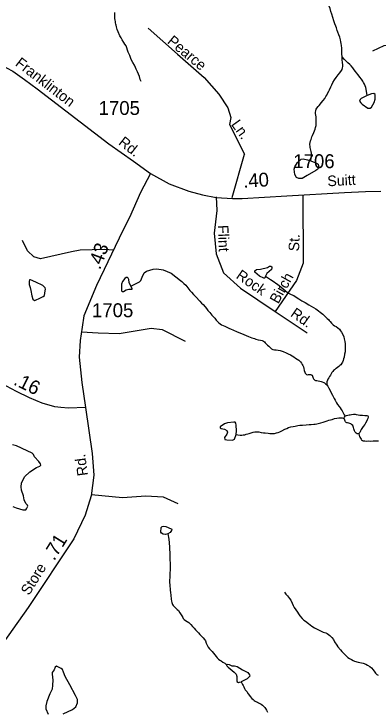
# Model space of a CAD drawing. Extents: x 2056842 to 2160602, y 826753 to 1016856.
# Drawn here: x 2133459 to 2136734, y 858350 to 864623 of the extents above; entities that cross this region are included whole.
import ezdxf

# ---------------------------------------------------------------- set-up
doc = ezdxf.new("R2010")
doc.units = 0
for name, color, linetype in [('Exist Hydrographic Creek Single Shore', 7, 'Continuous'), ('Exist Hydrographic Misc Water Feature', 7, 'Continuous'), ('Exist Road Non-System Type 51', 7, 'Continuous'), ('Exist Road Non-System Type 51 Label', 7, 'Continuous'), ('Exist Road Secondary Mileage Hundredths English Label', 7, 'Continuous'), ('Exist Road Secondary Type 51 Attributed', 7, 'Continuous'), ('Exist Road Secondary Type 51 Label', 7, 'Continuous'), ('Exist Road Secondary Type 51 Number Label', 7, 'Continuous')]:
    doc.layers.add(name, color=color, linetype=linetype)

msp = doc.modelspace()

# ---------------------------------------------------------------- linework, layer by layer
at = {"layer": 'Exist Hydrographic Creek Single Shore'}
for points in [[(2134842.5, 859943.7), (2134851, 859895.1), (2134858.3, 859827), (2134862, 859754), (2134865.6, 859637.3), (2134859.6, 859505.7), (2134860, 859486), (2134864.5, 859438.3), (2134866.5, 859416.1), (2134868.8, 859393.9), (2134873.1, 859357.7), (2134875.4, 859339.7), (2134879.5, 859326.5), (2134885.6, 859310), (2134891.6, 859300), (2134897.9, 859292.4), (2134909.8, 859280.8), (2134927.9, 859264.8), (2134937.9, 859254.8), (2134950.4, 859234.8), (2134958.2, 859223.1), (2134968.5, 859206.5), (2134976.7, 859190.8), (2134982.6, 859183.2), (2134990.6, 859174.9), (2135002.9, 859164.8), (2135016.9, 859155.5), (2135032.8, 859145.3), (2135049.2, 859129.4), (2135065.2, 859111.8), (2135079.4, 859095.9), (2135093.3, 859080.1), (2135105.6, 859065.9), (2135117.7, 859053.3), (2135129.8, 859040), (2135146.2, 859024.1), (2135161.6, 859008.1), (2135172.5, 858994.9), (2135180.5, 858980.7), (2135188.7, 858960.8), (2135196.7, 858942.6), (2135206.9, 858925.2), (2135217.2, 858911), (2135229.5, 858897.7), (2135241.2, 858885.2), (2135255.1, 858869.3), (2135265.6, 858855.1), (2135277.1, 858840.1), (2135287.9, 858830), (2135299.8, 858817.4), (2135311.9, 858808.2), (2135323, 858800.6), (2135338.2, 858790.5), (2135354.4, 858780.3), (2135369.1, 858770.1)], [(2135369.1, 858770.1), (2135377.3, 858771.4), (2135395.5, 858768.9), (2135419.8, 858758), (2135442.9, 858758), (2135467.2, 858750.7), (2135514.6, 858720.3), (2135563.3, 858697.2), (2135577.8, 858675.3), (2135580.3, 858664.4), (2135573, 858653.4), (2135557.2, 858640), (2135520.7, 858620.6), (2135503.8, 858613.2)], [(2135369.1, 858770.1), (2135374.9, 858758), (2135387, 858743.4), (2135439.3, 858698.4), (2135458.7, 858681.4), (2135463.6, 858659.5), (2135464.8, 858616.9), (2135478.2, 858607.2), (2135489.1, 858608.4), (2135503.8, 858613.2)], [(2135503.8, 858613.2), (2135515.9, 858589.9), (2135519.8, 858580), (2135526.4, 858566.7), (2135534.2, 858551.8), (2135540.1, 858541.8), (2135552.4, 858524.3), (2135566.6, 858504.4), (2135578.7, 858488.5), (2135584.8, 858480.2), (2135598.6, 858463.5), (2135609.9, 858453.5), (2135618.7, 858445.1), (2135630, 858439.1), (2135641.2, 858433.2), (2135649.2, 858428.9), (2135658.9, 858423.7), (2135669.3, 858418.6), (2135682.2, 858411.8), (2135693.3, 858403.3), (2135703.6, 858394.9), (2135715.7, 858381.5), (2135721.6, 858373.2), (2135731.9, 858357.4), (2135740.1, 858339.2)]]:
    msp.add_lwpolyline(points, dxfattribs=at)
at = {"layer": 'Exist Hydrographic Misc Water Feature'}
for points in [[(2136411.2, 864238.2), (2136409.2, 864264.5), (2136408.9, 864292.5), (2136406.7, 864314.6), (2136404.4, 864340.1), (2136402.4, 864356.6), (2136399.3, 864373.1), (2136395.4, 864390.3), (2136388.9, 864415.1), (2136381.7, 864435.7), (2136373.5, 864458.1), (2136367.3, 864473.7), (2136358.9, 864497.6), (2136353.2, 864511.7), (2136344.2, 864532.8), (2136334.7, 864560.5), (2136325.9, 864589.6), (2136317.1, 864619.4), (2136308.7, 864645.9), (2136301.7, 864670.9), (2136294.7, 864692.7), (2136277.7, 864722.1), (2136255.4, 864746), (2136226.7, 864772.8)], [(2134602.2, 864014.8), (2134595.9, 864033), (2134587.7, 864060.3), (2134579.7, 864080.1), (2134570.5, 864102.4), (2134559.2, 864126.4), (2134551.2, 864142.2), (2134543, 864160.4), (2134528.6, 864186.2), (2134514.5, 864214.3), (2134506.1, 864231.7), (2134500.1, 864249.8), (2134494, 864265.5), (2134487.8, 864279.7), (2134481.7, 864297.8), (2134475.7, 864317.6), (2134467.3, 864335.8), (2134457.1, 864351.6), (2134447.2, 864365.8), (2134432.9, 864389.1), (2134422.8, 864407.3), (2134412.6, 864427.2), (2134396.4, 864461.1), (2134388.2, 864482.7), (2134381.2, 864507.1), (2134377.9, 864522.3), (2134375.7, 864532.1), (2134373.6, 864543.5), (2134371.3, 864553.8), (2134369.1, 864566.7), (2134367.5, 864582), (2134366.8, 864600.4), (2134366.6, 864618), (2134366.6, 864637.3)], [(2136129, 863301.5), (2136135.2, 863351.6), (2136135.2, 863369.6), (2136132.9, 863383.6), (2136129.9, 863396.8), (2136126.6, 863409.9), (2136124.5, 863419.9), (2136122.5, 863432.2), (2136120.4, 863443.8), (2136120.4, 863452), (2136122.1, 863465.8), (2136126.2, 863479.7), (2136131.9, 863493.5), (2136139.7, 863515.5), (2136145.7, 863530.1), (2136155.3, 863556.2), (2136161, 863571.6), (2136167.2, 863586.3), (2136171.1, 863600.1), (2136176.8, 863619.8), (2136178.7, 863638.6), (2136178.5, 863654.2), (2136178.5, 863666.5), (2136178.5, 863682), (2136176.2, 863696), (2136174, 863712.5), (2136171.9, 863726.4), (2136172.1, 863739.6), (2136173.5, 863750.2), (2136178.1, 863765.7), (2136183.4, 863776.3), (2136195.1, 863790), (2136203.1, 863798), (2136215.2, 863812.6), (2136223, 863822.2), (2136240.2, 863843.1), (2136254.5, 863862.5), (2136264.6, 863878.8), (2136272.4, 863893.3), (2136280.4, 863907.2), (2136290.2, 863927.5), (2136296, 863939.7), (2136309.7, 863967.2), (2136319.5, 863985.9), (2136328.4, 864004.6), (2136342.7, 864028.9), (2136357.5, 864051.5), (2136374.9, 864074.1), (2136388.6, 864091.9), (2136404.4, 864114.5), (2136410.4, 864124.2), (2136414.5, 864137.3), (2136416.1, 864150.4), (2136415.9, 864161.9), (2136413.7, 864188.1), (2136411.6, 864207.9), (2136411.4, 864221.8), (2136411.2, 864238.2)], [(2136635.9, 863890.1), (2136627.9, 863945.9), (2136623.4, 863960.7), (2136617.5, 863975.7), (2136611.3, 863989.7), (2136603.3, 864006.3), (2136597.2, 864017.8), (2136586.1, 864035.3), (2136570.9, 864055.3), (2136556, 864074.5), (2136540.4, 864093.7), (2136532.4, 864105.4), (2136520.3, 864121.2), (2136506.1, 864138.7), (2136491.8, 864157), (2136479.9, 864168.7), (2136461.6, 864183.1), (2136453.7, 864190.7), (2136443.6, 864200.6), (2136431.3, 864214), (2136411.2, 864238.2)], [(2136635.9, 863890.1), (2136582.4, 863863.4), (2136573.9, 863852.4), (2136567.8, 863839.1), (2136577.5, 863822), (2136589.7, 863809.9), (2136643.2, 863774.6), (2136661.4, 863774.6), (2136673.5, 863783.1), (2136700.3, 863826.9), (2136707.6, 863857.3), (2136706.4, 863898.6), (2136695.4, 863908.4), (2136673.5, 863904.7), (2136635.9, 863890.1)], [(2136129, 863301.5), (2136186.2, 863278.4), (2136194.7, 863269.9), (2136198.3, 863257.7), (2136198.3, 863245.6), (2136191, 863227.3), (2136172.8, 863212.7), (2136096.2, 863167.7), (2136050, 863143.4), (2136020.9, 863141), (2136001.4, 863150.7), (2135986.8, 863178.7), (2135978.3, 863226.1), (2135984.4, 863246.8), (2136009.9, 863286.9), (2136041.5, 863317.3), (2136059.7, 863319.8), (2136098.6, 863311.2), (2136129, 863301.5)], [(2134510.9, 862172.9), (2134587.5, 862211.9), (2134599.7, 862224), (2134611.8, 862253.2), (2134631.9, 862293.3), (2134650.1, 862307.9), (2134712.1, 862327.4), (2134744.9, 862329.8), (2134800.8, 862318.9), (2134872.5, 862290.9), (2134955.9, 862225.1), (2134967.8, 862215.1), (2134987.9, 862197.5), (2135004.1, 862181.6), (2135024.4, 862158.2), (2135042.5, 862134), (2135056.6, 862118.1), (2135074.9, 862098), (2135095, 862076.3), (2135131.5, 862038.7), (2135145.6, 862021.1), (2135159.6, 862007), (2135177.8, 861986.9), (2135190.1, 861971), (2135204.1, 861953.5), (2135220.1, 861935.9), (2135238.3, 861913.5), (2135264.6, 861884.1), (2135278.9, 861868.3), (2135290.8, 861854.1), (2135302.9, 861842.3), (2135313.2, 861834.7), (2135325.9, 861826.3), (2135354.4, 861812.6), (2135393.3, 861795.4), (2135411.6, 861787.6), (2135427.6, 861781.5), (2135467.6, 861763.5), (2135489.9, 861754), (2135526, 861738.5), (2135546.3, 861729.8), (2135568.2, 861720.4), (2135582.2, 861714.4), (2135598.2, 861709.1), (2135622.2, 861701.2), (2135634.1, 861696.8), (2135656.4, 861691.5), (2135676.3, 861687.8), (2135692.3, 861683.4), (2135704.6, 861678.3), (2135711.2, 861672.3), (2135718.7, 861664), (2135726.7, 861654), (2135738.8, 861642.3), (2135750.9, 861632.1), (2135759.1, 861624.7), (2135769.2, 861616.1), (2135777, 861610.3), (2135787.2, 861604.4), (2135801.2, 861600.8), (2135817.2, 861598.8), (2135835.6, 861596.8), (2135853.1, 861593.1), (2135879.1, 861585.2), (2135907.4, 861573.9), (2135925.4, 861565.4), (2135945.7, 861554.3), (2135961.7, 861545.7), (2135977.7, 861536.5), (2135991.9, 861526.2), (2136020, 861506.8), (2136036, 861492.6), (2136046.2, 861479.3), (2136052.4, 861469.2), (2136058.3, 861459.3), (2136063.4, 861446.1), (2136066.7, 861431.3), (2136070.4, 861415.6), (2136074.9, 861400.7), (2136078.4, 861391.6), (2136083.7, 861384.1), (2136091.7, 861378.2), (2136101.6, 861376.3), (2136108.1, 861377.1), (2136114.7, 861378.6), (2136121.7, 861379.2), (2136127.8, 861379.1), (2136133.6, 861376.5), (2136141.6, 861371.4)], [(2135722.5, 862262.9), (2135715.2, 862245.9), (2135706.7, 862244.7), (2135667.8, 862261.7), (2135626.5, 862299.4), (2135626.5, 862311.6), (2135639.8, 862322.5), (2135677.5, 862327.4), (2135739.5, 862342), (2135758.9, 862352.9), (2135768.7, 862352.9), (2135777.2, 862346.8), (2135779.6, 862335.9), (2135774.7, 862322.5), (2135734.6, 862287.3), (2135727.3, 862276.3), (2135722.5, 862262.9)], [(2134510.9, 862172.9), (2134496, 862205.2), (2134492.4, 862233.7), (2134487.5, 862245.9), (2134479.6, 862251.4), (2134467.5, 862251.4), (2134455.3, 862242.9), (2134434.7, 862216.1), (2134426.2, 862192.4), (2134426.2, 862172.9), (2134428, 862131), (2134435.3, 862125.5), (2134443.8, 862126.1), (2134468.1, 862140.1), (2134493, 862147.4), (2134518.5, 862145), (2134522.2, 862147.4), (2134521.6, 862152.9), (2134510.9, 862172.9)], [(2135722.5, 862262.9), (2135767.3, 862232.2), (2135799.7, 862211), (2135815.9, 862200.8), (2135829.9, 862190.7), (2135862.1, 862163), (2135898.4, 862133.5), (2135922.6, 862114.2), (2135934.7, 862105.7), (2135952.7, 862097.9), (2135975.1, 862087.7), (2135996.8, 862074.8), (2136022.4, 862059.7), (2136049.1, 862042.6), (2136077.4, 862027.3), (2136111.6, 862005.2), (2136131.7, 861993.3), (2136174, 861967.9), (2136198, 861950.2), (2136214.1, 861938.4), (2136236.1, 861920.6), (2136248.4, 861909), (2136260.5, 861897.2), (2136276.7, 861882.9), (2136286.7, 861872.9), (2136294.7, 861865.3), (2136302.9, 861855.3), (2136315.2, 861841.1), (2136331.2, 861825.2), (2136343.1, 861817.6), (2136357.5, 861809.1), (2136371.4, 861798.1), (2136385.6, 861785.5), (2136395.4, 861772.2), (2136403.6, 861759.8), (2136416.7, 861738.1), (2136426.2, 861716.6), (2136430.1, 861700.1), (2136434.4, 861674.7), (2136437.5, 861653.2), (2136439.3, 861629.4), (2136438.9, 861604), (2136437.5, 861582.7), (2136433.4, 861562.2), (2136427.6, 861534.5), (2136423.7, 861520.6), (2136419.2, 861503.5), (2136414.1, 861490.5), (2136408.1, 861480), (2136398.1, 861466.1), (2136389.9, 861458.1), (2136380, 861450.2), (2136369.2, 861442.2), (2136356.5, 861433.4), (2136350.7, 861429.4), (2136340.7, 861421.4), (2136332.9, 861413.4), (2136326.3, 861406.2), (2136318.9, 861395.7), (2136311.3, 861384.3), (2136305, 861373.1), (2136297.8, 861360.9), (2136290.8, 861349.5), (2136283.5, 861334.9), (2136279.4, 861326.7), (2136273.8, 861311.3), (2136272, 861296.6), (2136272, 861285.1)], [(2133612.1, 862133.6), (2133620.5, 862086.4), (2133630.7, 862055.2), (2133644.1, 862045.1), (2133654.3, 862046.8), (2133691.3, 862066.2), (2133723.4, 862078.8), (2133733.5, 862090.6), (2133736, 862110.9), (2133739.4, 862131.9), (2133743.6, 862147.1), (2133741.1, 862158.1), (2133720, 862180), (2133657.6, 862208.7), (2133607.9, 862231.4), (2133599.5, 862229.8), (2133595.3, 862219.6), (2133595.3, 862186.8), (2133604.5, 862160.6), (2133612.1, 862133.6)], [(2136141.6, 861371.4), (2136145.7, 861362.3), (2136147.9, 861354.9), (2136150.4, 861346.6), (2136153.9, 861339.2), (2136158, 861332.6), (2136165.1, 861327.5), (2136172.1, 861324.9), (2136184.2, 861323), (2136194.1, 861321.2), (2136208.8, 861317.6), (2136221.3, 861314.8), (2136232.2, 861311.3), (2136244.7, 861307), (2136251.7, 861302.7), (2136257.8, 861297.7), (2136265.2, 861291.9), (2136272, 861285.1)], [(2136272, 861285.1), (2136281.8, 861272.6), (2136292.1, 861256.8), (2136302.3, 861235.3), (2136310.3, 861219.5), (2136322.6, 861193), (2136338.8, 861161.5), (2136347.2, 861147.4), (2136359.3, 861123.3), (2136369.4, 861107.6), (2136383.7, 861090), (2136391.9, 861077.6), (2136402, 861064.2), (2136410, 861050.1), (2136424.1, 861026.1), (2136430.1, 861014.4), (2136436.6, 861002.8)], [(2136429.9, 860983.2), (2136429.7, 860989.8), (2136431.3, 860995.6), (2136436.6, 861002.8)], [(2136436.6, 861002.8), (2136441.6, 861006), (2136451.4, 861009.9), (2136461.4, 861012.2), (2136472.7, 861014.4), (2136483.4, 861016.7), (2136494.9, 861018.8), (2136511.5, 861021), (2136527.5, 861020.7), (2136537.3, 861018.7), (2136554.5, 861015.1), (2136571.4, 861013.1), (2136581.4, 861011.3), (2136595.3, 861011), (2136615.4, 861009.8), (2136631.4, 861007.9), (2136641.5, 861005.9), (2136645.4, 861001.8), (2136645.6, 860993.6), (2136641.7, 860981.4), (2136635.9, 860970), (2136631.8, 860961.9), (2136621.8, 860941.5), (2136614.2, 860929.4), (2136600.5, 860909.2), (2136593.9, 860901.1), (2136588.4, 860891.4), (2136582.6, 860882.5), (2136576.7, 860871.1), (2136572.6, 860863), (2136568.9, 860854.9), (2136564.8, 860849.2), (2136559.5, 860846.1)], [(2135458.7, 860837.1), (2135461.2, 860870.4), (2135458.7, 860922.7), (2135455.1, 860939.8), (2135447.8, 860948.3), (2135438.1, 860950.7), (2135379.7, 860942.2), (2135351.8, 860934.9), (2135315.3, 860908.1), (2135315.3, 860899.6), (2135322.6, 860893.5), (2135354.2, 860886.3), (2135374.9, 860874.1), (2135379.7, 860858.3), (2135372.4, 860842.5), (2135354.2, 860812.1), (2135356.6, 860792.6), (2135372.4, 860789), (2135425.9, 860786.5), (2135441.7, 860796.3), (2135458.7, 860837.1)], [(2135458.7, 860837.1), (2135474.1, 860834.9), (2135493.8, 860833.7), (2135508.2, 860833.4), (2135522.1, 860833.9), (2135536, 860836), (2135547.9, 860839.9), (2135561.9, 860844.5), (2135574, 860848.4), (2135591.8, 860854.6), (2135609.5, 860859.2), (2135625.9, 860862.9), (2135643.9, 860863.4), (2135661.7, 860861.3), (2135683.7, 860857.7), (2135703.6, 860854), (2135720, 860851.9), (2135745.8, 860849.8), (2135761.8, 860848.6), (2135783.3, 860847.4), (2135802.2, 860847.8), (2135821.9, 860853.1), (2135834, 860857), (2135849.6, 860863.2), (2135867.4, 860871.1), (2135895.3, 860885.2), (2135913.3, 860893.8), (2135929.3, 860900.1), (2135949.2, 860906.3), (2135970.3, 860911.6), (2135987.2, 860914.5), (2136013.2, 860918.9), (2136029.2, 860921), (2136053.2, 860923), (2136086.8, 860924.7), (2136113.1, 860927.5), (2136133.2, 860929.5), (2136157.1, 860931.5), (2136168.8, 860932.1), (2136182.6, 860934.2), (2136194.9, 860936.4), (2136218.9, 860942.5), (2136239, 860948.7), (2136258.6, 860956.4), (2136274.8, 860962.6), (2136290.6, 860967.3), (2136307, 860971), (2136320.6, 860974.8), (2136342.7, 860981.8), (2136362.6, 860985.5), (2136380.4, 860987.6), (2136392.5, 860988.2), (2136410.4, 860987.8), (2136429.9, 860983.2)], [(2136559.5, 860846.1), (2136552.9, 860844.5), (2136546.3, 860844.7), (2136536.7, 860850.6), (2136526.6, 860860.7), (2136520.7, 860872.3), (2136516.4, 860888.8), (2136514.1, 860901.1), (2136511.1, 860910.2), (2136506.1, 860918.6), (2136496.1, 860928.6), (2136488.1, 860934.5), (2136480.1, 860937.9), (2136470.1, 860940.6), (2136460.2, 860942.4), (2136453.9, 860944.2), (2136447.7, 860947.7), (2136442, 860951.9), (2136437.9, 860957.7), (2136433.6, 860965.9), (2136431.7, 860975.9), (2136429.9, 860983.2)], [(2136559.5, 860846.1), (2136564, 860829.6), (2136565.8, 860823), (2136570.1, 860815.5), (2136576.1, 860805.6), (2136582.2, 860795.5), (2136586.1, 860789.8), (2136594.1, 860783.8), (2136600.5, 860782.1), (2136614.2, 860780.1), (2136632.5, 860779.7), (2136648.4, 860780.2), (2136666.3, 860779.8), (2136690.5, 860780.1), (2136712.4, 860780.6), (2136736.4, 860780.9)], [(2133450.7, 860191.8), (2133478.7, 860179.7), (2133538.2, 860161.4), (2133566.2, 860160.2), (2133573.5, 860169.9), (2133584.4, 860193.1), (2133582, 860201.6), (2133566.2, 860217.4), (2133551.6, 860250.2), (2133544.3, 860287.9), (2133526.1, 860336.6), (2133523.6, 860367), (2133527.3, 860401), (2133555.2, 860458.2), (2133602.6, 860502), (2133661, 860540.9), (2133692.6, 860554.3), (2133699.9, 860562.8), (2133698.7, 860573.7), (2133682.9, 860595.6), (2133642.8, 860638.2), (2133635.5, 860658.8), (2133623.3, 860669.8), (2133579.6, 860690.5), (2133481.1, 860735.5), (2133447.1, 860744)], [(2134842.5, 859943.7), (2134823.1, 859937.7), (2134802.4, 859941.3), (2134785.4, 859951), (2134780.5, 859960.8), (2134782.9, 860000.9), (2134792.7, 860010.6), (2134804.8, 860014.3), (2134824.3, 860011.8), (2134872.9, 859990), (2134877.8, 859985.1), (2134876.5, 859975.4), (2134863.2, 859955.9), (2134842.5, 859943.7)], [(2135892.4, 859418.8), (2135904.7, 859402.9), (2135920.9, 859385.3), (2135936.9, 859363.6), (2135949.2, 859347.9), (2135961.3, 859321.4), (2135971.6, 859299.9), (2135979.6, 859281.6), (2135993.9, 859260), (2136008.1, 859240), (2136018.1, 859224.2), (2136030.4, 859206.7), (2136050.7, 859182.5), (2136066.7, 859168.3), (2136082.7, 859158.9), (2136109, 859138.7), (2136139.1, 859115.1), (2136163.1, 859099.8), (2136191.4, 859083.6), (2136241.6, 859060.5), (2136263.6, 859052.7), (2136275.7, 859046.7), (2136287.6, 859038.2), (2136299.9, 859028.9), (2136318.1, 859010.5), (2136332.1, 858993), (2136342.3, 858971.5), (2136362.6, 858941.5), (2136372.7, 858927.3), (2136394.8, 858899.9), (2136407.1, 858885.6), (2136419.2, 858873.9), (2136429, 858863.9), (2136447.7, 858846.2), (2136461.6, 858832), (2136477.6, 858822.7), (2136493.8, 858812.5), (2136509.8, 858804.8), (2136521.9, 858798.8), (2136554.1, 858789.1), (2136569.9, 858785.5), (2136600.7, 858779.9), (2136624, 858771.2), (2136640, 858761.9), (2136660.1, 858750), (2136674.3, 858738.2), (2136688.4, 858719.9), (2136704.6, 858699.9), (2136710.8, 858690.8), (2136722.9, 858678.2), (2136735, 858672.2)], [(2133901.8, 858325.1), (2133986.8, 858362.8), (2134014.8, 858388.3), (2134031.8, 858423.6), (2134031.8, 858455.2), (2134013.6, 858490.5), (2133961.3, 858586.5), (2133918.8, 858660.7), (2133905.4, 858698.4), (2133896.9, 858722.7), (2133884.7, 858733.7), (2133842.2, 858753.1), (2133831.3, 858744.6), (2133820.3, 858721.5), (2133804.5, 858697.2), (2133803.3, 858680.2), (2133809.4, 858627.9), (2133807, 858581.7), (2133803.3, 858546.4), (2133781.4, 858505), (2133754.7, 858434.5), (2133745, 858398), (2133745, 858368.8), (2133768.1, 858321.4)]]:
    msp.add_lwpolyline(points, dxfattribs=at)
at = {"layer": 'Exist Road Non-System Type 51'}
for p, q in [((2135421.2, 862969.9), (2135534.1, 863361.7)), ((2135808.2, 861944.2), (2136094.9, 861753))]:
    msp.add_line(p, q, dxfattribs=at)
for points in [[(2134667.7, 864493.4), (2134929.2, 864261.7), (2135169.3, 864051.5), (2135302.2, 863901.3), (2135383.6, 863776.9), (2135409.3, 863691.1), (2135396.5, 863626.8), (2135534.1, 863361.7)], [(2137259.4, 864211.8), (2137033.8, 864295.7), (2136888.4, 864341.4), (2136784.6, 864337.3), (2136684.9, 864287.4)], [(2136057.8, 862996.3), (2136061.6, 862380.7), (2135999.3, 862222.7), (2135808.2, 861944.2)], [(2135276.7, 862976.8), (2135284.8, 862854.6), (2135259.9, 862650.9), (2135276.5, 862463.9), (2135343, 862293.4), (2135496.7, 862156.2), (2135808.2, 861944.2)], [(2134354, 862496.7), (2134270.2, 862504.4), (2134056.3, 862496.1), (2133977.4, 862483.6), (2133699, 862419.2), (2133638.8, 862437.9), (2133580.7, 862491.9), (2133535, 862585.4)], [(2134067, 861762.3), (2134217.3, 861753), (2134406.3, 861746.8), (2134692.9, 861794.6), (2134792.6, 861782.1), (2134999.3, 861679.2)], [(2134157.7, 860298.4), (2134435.3, 860271.1), (2134645.1, 860285.6), (2134800.9, 860277.3), (2134931.7, 860217.1)]]:
    msp.add_lwpolyline(points, dxfattribs=at)
at = {"layer": 'Exist Road Secondary Type 51 Attributed'}
for points in [[(2131854.6, 864428.3), (2131934.3, 864422.3), (2132035.2, 864414.7), (2132128.2, 864417.7), (2132183.8, 864417.7), (2132251.5, 864406.9), (2132303.4, 864394.8), (2132377.1, 864368.2), (2132524.5, 864298.1), (2132664.6, 864240.8), (2132712.9, 864223.8), (2132783, 864206.9), (2133112.8, 864197.9), (2133216.7, 864189.4), (2133302.5, 864173.1), (2133393.1, 864138.1), (2133448.6, 864106.7), (2133554.9, 864031.8), (2133668.5, 863949), (2134312.3, 863453.9), (2134533.7, 863297), (2134688.1, 863187.3)], [(2134688.1, 863187.3), (2134596.9, 863017.1), (2134498.4, 862789.8), (2134439.1, 862672.9), (2134200.7, 862179.4), (2134088.5, 861907.5), (2134074.3, 861803.9), (2134053.4, 861684.1), (2134045.8, 861533.9), (2134070.5, 861305.7), (2134102.8, 861080.3)], [(2134688.1, 863187.3), (2134854.8, 863095.5), (2135031.2, 863027.8), (2135155.6, 862994.6), (2135278.8, 862971.6), (2135425, 862960.8), (2135510.7, 862962), (2135913.7, 862984.7), (2136431.3, 863015.7), (2136619.7, 863025.4), (2136759.9, 863029)], [(2134102.8, 861080.3), (2133950.6, 861075.1), (2133881.9, 861081), (2133825.7, 861087.5), (2133713.9, 861120.7), (2133598.1, 861167.1), (2133483.7, 861225), (2133392.8, 861273.3), (2133328.1, 861302.2), (2133248.2, 861329.7), (2133201.4, 861340.8), (2133171.1, 861343.5), (2133133.9, 861346.3), (2133016.8, 861351.8), (2132921.8, 861371.1)], [(2134102.8, 861080.3), (2134162.6, 860667.7), (2134177.9, 860471.8), (2134154.1, 860286.4), (2134100.9, 860111.5), (2133998.3, 859898.5), (2133586.9, 859281.5), (2133082.4, 858573.2), (2132805.7, 858223.3), (2132747, 858066.4), (2132729.9, 857954.2), (2132719.6, 857812), (2132718.8, 857784.3)]]:
    msp.add_lwpolyline(points, dxfattribs=at)

# ---------------------------------------------------------------- texts
at = {"layer": 'Exist Road Non-System Type 51 Label'}
for s, rotation, p in [('Pearce', 320.19821, (2134831.5, 864365.2)), ('Ln.', 305.5765, (2135408.3, 863628.7)), ('Flint', 272.11891, (2135292.7, 862721.9)), ('St.', 87.66428, (2136023, 862485.2)), ('Rock', 325.18621, (2135449.5, 862250.3)), ('Birch', 60.65471, (2135835.7, 862008)), ('Rd.', 324.88614, (2135939.5, 861908.4))]:
    msp.add_text(s, height=95, rotation=rotation, dxfattribs=at).set_placement(p)
at = {"layer": 'Exist Road Secondary Mileage Hundredths English Label'}
for s, rotation, p in [('.40', 3.5176, (2135523.9, 863057.8)), ('.43', 69.41537, (2134233.7, 862314.6)), ('.16', 333.91323, (2133447.4, 861291)), ('.71', 58.1413, (2133821.1, 859695.9))]:
    msp.add_text(s, height=125, rotation=rotation, dxfattribs=at).set_placement(p)
at = {"layer": 'Exist Road Secondary Type 51 Label'}
for s, rotation, p in [('Franklinton', 322.40109, (2133464.4, 864164.3)), ('Rd.', 322.04069, (2134392.2, 863453.4)), ('Suitt', 3.06629, (2136280.4, 863071.6)), ('Rd.', 97.66468, (2134125.6, 860471.6)), ('Store', 58.36191, (2133595.2, 859384.7))]:
    msp.add_text(s, height=95, rotation=rotation, dxfattribs=at).set_placement(p)
at = {"layer": 'Exist Road Secondary Type 51 Number Label'}
for s, p in [('1705', (2134220.8, 863714.1)), ('1706', (2135971.4, 863235.2)), ('1705', (2134161.2, 861894.1))]:
    msp.add_text(s, height=125, dxfattribs=at).set_placement(p)

doc.saveas('drawing.dxf')
